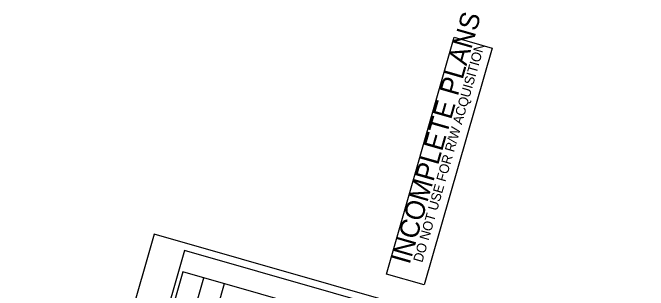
# Model space of a CAD drawing. Extents: x 2096093 to 2098911, y 683546 to 689764.
# Drawn here: x 2097369.3 to 2097748.3, y 689598.1 to 689763.7 of the extents above; entities that cross this region are included whole.
import ezdxf

# ---------------------------------------------------------------- set-up
doc = ezdxf.new("R2010")
doc.units = 0
for name, color, linetype in [('Default', 7, 'Continuous'), ('Sheet Plan CELL', 7, 'Continuous'), ('Sheet Plot Border Inside CELL', 7, 'Continuous'), ('Sheet Plot Border Outside CELL', 7, 'Continuous'), ('Sheet Sticker Incomplete CELL', 7, 'Continuous')]:
    doc.layers.add(name, color=color, linetype=linetype)

msp = doc.modelspace()

# ---------------------------------------------------------------- linework, layer by layer
at = {"layer": 'Default'}
for p, q in [((2097463.95, 689538.15), (2097483.29, 689605.65)), ((2097463.95, 689538.15), (2097483.29, 689605.65)), ((2097444.05, 689422.43), (2097495.53, 689602.15)), ((2097444.05, 689422.43), (2097495.53, 689602.15))]:
    msp.add_line(p, q, dxfattribs=at)
at = {"layer": 'Sheet Plan CELL'}
msp.add_lwpolyline([(2097470.8, 689609.08), (2097057.86, 688167.12), (2098067.29, 687878.05), (2098480.22, 689319.99)], close=True, dxfattribs=at)
at = {"layer": 'Sheet Plot Border Inside CELL'}
msp.add_lwpolyline([(2098027.26, 687729.7), (2098485.9, 689331.31), (2097471.68, 689621.77), (2097013.02, 688020.15)], close=True, dxfattribs=at)
msp.add_lwpolyline([(2098027.26, 687729.7), (2098485.9, 689331.31), (2097471.68, 689621.77), (2097013.02, 688020.15)], close=True, dxfattribs=at)
at = {"layer": 'Sheet Plot Border Outside CELL'}
msp.add_lwpolyline([(2098042.9, 687711.7), (2098506.38, 689330.14), (2097453.69, 689631.6), (2096990.22, 688013.15)], close=True, dxfattribs=at)
msp.add_lwpolyline([(2098042.9, 687711.7), (2098506.38, 689330.14), (2097453.69, 689631.6), (2096990.22, 688013.15)], close=True, dxfattribs=at)
at = {"layer": 'Sheet Sticker Incomplete CELL'}
msp.add_lwpolyline([(2097614.71, 689601.31), (2097592.11, 689607.78), (2097632.58, 689749.1), (2097655.18, 689742.63)], close=True, dxfattribs=at)
msp.add_lwpolyline([(2097614.71, 689601.31), (2097592.11, 689607.78), (2097632.58, 689749.1), (2097655.18, 689742.63)], close=True, dxfattribs=at)

# ---------------------------------------------------------------- texts
for s, height, p in [('INCOMPLETE PLANS', 11.52, (2097605.92, 689613.13)), ('INCOMPLETE PLANS', 11.52, (2097605.92, 689613.13)), ('DO NOT USE FOR R/W ACQUISITION', 5.76, (2097613.5, 689614.34)), ('DO NOT USE FOR R/W ACQUISITION', 5.76, (2097613.5, 689614.34))]:
    msp.add_text(s, height=height, rotation=74.0199, dxfattribs=at).set_placement(p)

doc.saveas('drawing.dxf')
